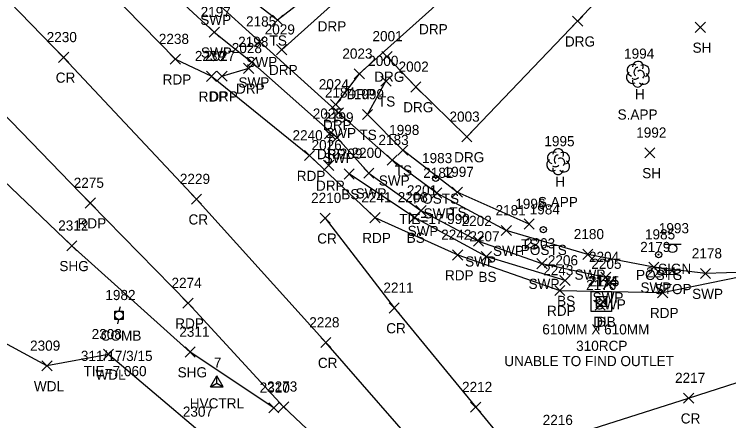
# Model space of a CAD drawing. Extents: x 1616726 to 1619875, y 273782 to 276557.
# Drawn here: x 1616834.7 to 1616975.5, y 276373.3 to 276453.4 of the extents above; entities that cross this region are included whole.
import ezdxf

# ---------------------------------------------------------------- set-up
doc = ezdxf.new("R2010")
doc.units = 0
for name, color, linetype in [('C_A', 7, 'Continuous'), ('C_I', 7, 'Continuous'), ('CPSM', 7, 'Continuous'), ('D_A', 7, 'Continuous'), ('D_C', 7, 'Continuous'), ('D_I', 7, 'Continuous'), ('D_TIC', 7, 'Continuous'), ('DS', 7, 'Continuous'), ('L_A', 7, 'Continuous'), ('L_C', 7, 'Continuous'), ('L_I', 7, 'Continuous'), ('L_TIC', 7, 'Continuous'), ('LAWA', 7, 'Continuous'), ('LELB', 7, 'Continuous'), ('LPST', 7, 'Continuous'), ('LTD', 7, 'Continuous'), ('P_A', 7, 'Continuous'), ('P_I', 7, 'Continuous'), ('P_TIC', 7, 'Continuous'), ('PET', 7, 'Continuous'), ('PRC', 7, 'Continuous'), ('PSU', 7, 'Continuous'), ('R_A', 7, 'Continuous'), ('R_I', 7, 'Continuous'), ('R_TIC', 7, 'Continuous'), ('RDG', 7, 'Continuous'), ('RDP', 7, 'Continuous'), ('RSW', 7, 'Continuous'), ('S_A', 7, 'Continuous'), ('S_C', 7, 'Continuous'), ('S_I', 7, 'Continuous'), ('SSGN', 7, 'Continuous'), ('U_A', 7, 'Continuous'), ('U_C', 7, 'Continuous'), ('U_I', 7, 'Continuous'), ('UP', 7, 'Continuous')]:
    doc.layers.add(name, color=color, linetype=linetype)

msp = doc.modelspace()

# ---------------------------------------------------------------- linework, layer by layer
at = {"layer": 'CPSM'}
for p, q in [((1616873.34, 276379.99), (1616874.59, 276382.16)), ((1616873.34, 276379.99), (1616874.59, 276382.16)), ((1616873.34, 276379.99), (1616874.59, 276382.16)), ((1616873.34, 276379.99), (1616874.59, 276382.16)), ((1616875.84, 276379.99), (1616874.59, 276382.16)), ((1616874.59, 276380.71), (1616874.59, 276382.16)), ((1616875.84, 276379.99), (1616874.59, 276382.16)), ((1616874.59, 276380.71), (1616874.59, 276382.16)), ((1616875.84, 276379.99), (1616874.59, 276382.16)), ((1616874.59, 276380.71), (1616874.59, 276382.16)), ((1616875.84, 276379.99), (1616874.59, 276382.16)), ((1616874.59, 276380.71), (1616874.59, 276382.16)), ((1616873.34, 276379.99), (1616874.59, 276380.71)), ((1616873.34, 276379.99), (1616874.59, 276380.71)), ((1616873.34, 276379.99), (1616874.59, 276380.71)), ((1616873.34, 276379.99), (1616874.59, 276380.71)), ((1616874.59, 276380.71), (1616874.59, 276380.71)), ((1616874.59, 276380.71), (1616875.84, 276379.99)), ((1616874.59, 276380.71), (1616874.59, 276380.71)), ((1616874.59, 276380.71), (1616875.84, 276379.99)), ((1616874.59, 276380.71), (1616874.59, 276380.71)), ((1616874.59, 276380.71), (1616875.84, 276379.99)), ((1616874.59, 276380.71), (1616874.59, 276380.71)), ((1616874.59, 276380.71), (1616875.84, 276379.99)), ((1616873.34, 276379.99), (1616875.84, 276379.99)), ((1616873.34, 276379.99), (1616875.84, 276379.99)), ((1616873.34, 276379.99), (1616875.84, 276379.99)), ((1616873.34, 276379.99), (1616875.84, 276379.99))]:
    msp.add_line(p, q, dxfattribs=at)
at = {"layer": 'D_TIC'}
for points in [[(1616949.69, 276395.76), (1616951.69, 276397.76)], [(1616951.69, 276395.76), (1616949.69, 276397.76)], [(1616949.15, 276395.04), (1616951.15, 276397.04)], [(1616951.15, 276395.04), (1616949.15, 276397.04)]]:
    msp.add_lwpolyline(points, dxfattribs=at)
at = {"layer": 'DS'}
for p, q in [((1616948.42, 276398.78), (1616952.42, 276398.78)), ((1616948.42, 276394.78), (1616948.42, 276398.78)), ((1616949.42, 276395.78), (1616949.42, 276397.78)), ((1616949.42, 276397.78), (1616951.42, 276397.78)), ((1616951.42, 276397.78), (1616951.42, 276395.78)), ((1616952.42, 276398.78), (1616952.42, 276394.78)), ((1616950.42, 276396.78), (1616950.42, 276396.78)), ((1616950.42, 276396.78), (1616950.42, 276396.78)), ((1616952.42, 276394.78), (1616948.42, 276394.78)), ((1616951.42, 276395.78), (1616949.42, 276395.78))]:
    msp.add_line(p, q, dxfattribs=at)
at = {"layer": 'L_TIC'}
for points in [[(1616885.59, 276451.23), (1616887.59, 276453.23)], [(1616887.59, 276451.23), (1616885.59, 276453.23)], [(1616968.9, 276449.81), (1616970.9, 276451.81)], [(1616970.9, 276449.81), (1616968.9, 276451.81)], [(1616906.95, 276439.21), (1616908.95, 276441.21)], [(1616908.95, 276439.21), (1616906.95, 276441.21)], [(1616903.32, 276432.64), (1616905.32, 276434.64)], [(1616905.32, 276432.64), (1616903.32, 276434.64)], [(1616910.27, 276425.6), (1616912.27, 276427.6)], [(1616912.27, 276425.6), (1616910.27, 276427.6)], [(1616958.96, 276425.08), (1616960.96, 276427.08)], [(1616960.96, 276425.08), (1616958.96, 276427.08)], [(1616899.7, 276420.92), (1616901.7, 276422.92)], [(1616901.7, 276420.92), (1616899.7, 276422.92)], [(1616921.01, 276417.34), (1616923.01, 276419.34)], [(1616923.01, 276417.34), (1616921.01, 276419.34)], [(1616912.6, 276412.34), (1616914.6, 276414.34)], [(1616914.6, 276412.34), (1616912.6, 276414.34)], [(1616935.18, 276411.04), (1616937.18, 276413.04)], [(1616937.18, 276411.04), (1616935.18, 276413.04)], [(1616926.73, 276404.63), (1616928.73, 276406.63)], [(1616928.73, 276404.63), (1616926.73, 276406.63)], [(1616942.24, 276399.9), (1616944.24, 276401.9)], [(1616944.24, 276399.9), (1616942.24, 276401.9)], [(1616852.28, 276385.36), (1616854.28, 276387.36)], [(1616854.28, 276385.36), (1616852.28, 276387.36)], [(1616840.14, 276383.08), (1616842.14, 276385.08)], [(1616842.14, 276383.08), (1616840.14, 276385.08)]]:
    msp.add_lwpolyline(points, dxfattribs=at)
at = {"layer": 'LAWA'}
msp.add_lwpolyline([(1616926.41, 276312.56), (1616914.58, 276324.87), (1616905.26, 276338.6), (1616897.95, 276344.34), (1616892.13, 276347.37), (1616881.86, 276360.64), (1616871.25, 276371.07), (1616853.28, 276386.36), (1616841.14, 276384.08), (1616808.16, 276401.96), (1616800.62, 276406.17), (1616775.17, 276427.7), (1616751.6, 276451.28), (1616729.6, 276454.6)], dxfattribs=at)
at = {"layer": 'LELB'}
for points in [[(1616901.03, 276463.44), (1616886.59, 276452.23), (1616871.01, 276464.24)], [(1616936.18, 276412.04), (1616922.01, 276418.34), (1616911.27, 276426.6), (1616904.32, 276433.64), (1616907.95, 276440.21)], [(1616943.24, 276400.9), (1616927.73, 276405.63), (1616913.6, 276413.34), (1616900.7, 276421.92)]]:
    msp.add_lwpolyline(points, dxfattribs=at)
at = {"layer": 'LPST'}
for centre, radius in [((1616917.75, 276421.05), 0.625), ((1616917.75, 276421.05), 0.0833), ((1616938.97, 276410.94), 0.625), ((1616938.97, 276410.94), 0.0833), ((1616961.69, 276406.02), 0.625), ((1616961.69, 276406.02), 0.0833)]:
    msp.add_circle(centre, radius, dxfattribs=at)
at = {"layer": 'LTD'}
for p, q in [((1616957.57, 276441.64), (1616957.57, 276441.64)), ((1616957.57, 276441.64), (1616957.57, 276441.64)), ((1616941.86, 276424.38), (1616941.86, 276424.38)), ((1616941.86, 276424.38), (1616941.86, 276424.38))]:
    msp.add_line(p, q, dxfattribs=at)
for centre in [(1616957.62, 276443.07), (1616941.91, 276425.82)]:
    msp.add_arc(centre, 1.05, 335.5272, 180.9563, dxfattribs=at)
for centre, major_axis, ratio, start_param, end_param in [((1616956.78, 276442.3), (1.21, -0.51), 0.895232, 1.570796, 4.712389), ((1616957.37, 276442.1), (-0.208, -0.792), 0.645439, 3.141593, 6.283185), ((1616958.62, 276442.22), (-1.14, -0.48), 0.949671, 1.570796, 4.712389), ((1616956.49, 276440.93), (0.58, -1.04), 0.959034, 3.141593, 6.283185), ((1616958.07, 276441.47), (-0.5, 0.667), 0.989748, 3.141593, 6.283185), ((1616958.57, 276440.8), (-1.09, 0.79), 0.841452, 1.570796, 4.712389), ((1616957.57, 276440.14), (0.26, 1.06), 0.942809, 1.570796, 4.712389), ((1616957.12, 276440.89), (-0.625, -0.083), 0.423636, 0, 3.141593), ((1616941.07, 276425.05), (1.21, -0.51), 0.895232, 1.570796, 4.712389), ((1616941.65, 276424.84), (-0.208, -0.792), 0.645439, 3.141593, 6.283185), ((1616942.9, 276424.97), (-1.14, -0.48), 0.949671, 1.570796, 4.712389), ((1616940.78, 276423.68), (0.58, -1.04), 0.959034, 3.141593, 6.283185), ((1616942.36, 276424.22), (-0.5, 0.667), 0.989748, 3.141593, 6.283185), ((1616942.86, 276423.55), (-1.09, 0.79), 0.841452, 1.570796, 4.712389), ((1616941.86, 276422.88), (0.26, 1.06), 0.942809, 1.570796, 4.712389), ((1616941.4, 276423.63), (-0.625, -0.083), 0.423636, 0, 3.141593)]:
    msp.add_ellipse(centre, major_axis=major_axis, ratio=ratio, start_param=start_param, end_param=end_param, dxfattribs=at)
at = {"layer": 'P_TIC'}
for points in [[(1616843.42, 276443.9), (1616845.42, 276445.9)], [(1616845.42, 276443.9), (1616843.42, 276445.9)], [(1616865.44, 276443.54), (1616867.44, 276445.54)], [(1616867.44, 276443.54), (1616865.44, 276445.54)], [(1616872.55, 276440.17), (1616874.55, 276442.17)], [(1616874.55, 276440.17), (1616872.55, 276442.17)], [(1616891.87, 276424.54), (1616893.87, 276426.54)], [(1616893.87, 276424.54), (1616891.87, 276426.54)], [(1616848.67, 276415.18), (1616850.67, 276417.18)], [(1616850.67, 276415.18), (1616848.67, 276417.18)], [(1616869.6, 276415.95), (1616871.6, 276417.95)], [(1616871.6, 276415.95), (1616869.6, 276417.95)], [(1616904.78, 276412.31), (1616906.78, 276414.31)], [(1616906.78, 276412.31), (1616904.78, 276414.31)], [(1616894.97, 276412.2), (1616896.97, 276414.2)], [(1616896.97, 276412.2), (1616894.97, 276414.2)], [(1616845.05, 276406.76), (1616847.05, 276408.76)], [(1616847.05, 276406.76), (1616845.05, 276408.76)], [(1616921.09, 276404.95), (1616923.09, 276406.95)], [(1616923.09, 276404.95), (1616921.09, 276406.95)], [(1616941.2, 276397.95), (1616943.2, 276399.95)], [(1616943.2, 276397.95), (1616941.2, 276399.95)], [(1616961.48, 276397.53), (1616963.48, 276399.53)], [(1616963.48, 276397.53), (1616961.48, 276399.53)], [(1616867.94, 276395.45), (1616869.94, 276397.45)], [(1616869.94, 276395.45), (1616867.94, 276397.45)], [(1616908.57, 276394.51), (1616910.57, 276396.51)], [(1616910.57, 276394.51), (1616908.57, 276396.51)], [(1616895.09, 276387.68), (1616897.09, 276389.68)], [(1616897.09, 276387.68), (1616895.09, 276389.68)], [(1616868.35, 276385.82), (1616870.35, 276387.82)], [(1616870.35, 276385.82), (1616868.35, 276387.82)], [(1616966.61, 276376.73), (1616968.61, 276378.73)], [(1616968.61, 276376.73), (1616966.61, 276378.73)], [(1616884.84, 276374.81), (1616886.84, 276376.81)], [(1616886.84, 276374.81), (1616884.84, 276376.81)], [(1616886.78, 276375.03), (1616888.78, 276377.03)], [(1616888.78, 276375.03), (1616886.78, 276377.03)], [(1616924.64, 276374.94), (1616926.64, 276376.94)], [(1616926.64, 276374.94), (1616924.64, 276376.94)]]:
    msp.add_lwpolyline(points, dxfattribs=at)
at = {"layer": 'PET'}
for points in [[(1616787.59, 276521.58), (1616809.24, 276501.22), (1616830.38, 276480.01), (1616850.02, 276461.38), (1616866.44, 276444.54), (1616873.55, 276441.17), (1616892.87, 276425.54), (1616905.78, 276413.31), (1616922.09, 276405.95), (1616942.2, 276398.95), (1616962.48, 276398.53), (1616981.09, 276402.37)], [(1616900.38, 276364.1), (1616887.78, 276376.03), (1616868.94, 276396.45), (1616849.67, 276416.18), (1616824.34, 276442.26), (1616800.52, 276466.55), (1616781.83, 276484.67), (1616766.23, 276499.7)]]:
    msp.add_lwpolyline(points, dxfattribs=at)
at = {"layer": 'PRC'}
for points in [[(1616953.09, 276321.77), (1616937.3, 276341.18), (1616917.35, 276364.38), (1616896.09, 276388.68), (1616870.6, 276416.95), (1616844.42, 276444.9), (1616816.58, 276473.52), (1616795.84, 276493.99), (1616777.17, 276512.19)], [(1616941.59, 276369.44), (1616967.61, 276377.73), (1616992.45, 276385.73), (1617015.18, 276393.53), (1617040, 276403.88), (1617060.6, 276414.36), (1617077.78, 276424.7), (1617090.54, 276433.25), (1617097.77, 276438.74)], [(1616895.97, 276413.2), (1616909.57, 276395.51), (1616925.64, 276375.94), (1616938.47, 276360.41), (1616951.96, 276344.02), (1616962.87, 276330.95)]]:
    msp.add_lwpolyline(points, dxfattribs=at)
at = {"layer": 'PSU'}
msp.add_lwpolyline([(1616885.84, 276375.81), (1616869.35, 276386.82), (1616846.05, 276407.76), (1616827.94, 276424.97), (1616809.53, 276443.22), (1616786.02, 276468.38), (1616760.28, 276493.66)], dxfattribs=at)
at = {"layer": 'R_TIC'}
for points in [[(1616944.73, 276451.03), (1616946.73, 276453.03)], [(1616946.73, 276451.03), (1616944.73, 276453.03)], [(1616873.12, 276448.86), (1616875.12, 276450.86)], [(1616875.12, 276448.86), (1616873.12, 276450.86)], [(1616882.06, 276446.99), (1616884.06, 276448.99)], [(1616884.06, 276446.99), (1616882.06, 276448.99)], [(1616886.4, 276445.41), (1616888.4, 276447.41)], [(1616888.4, 276445.41), (1616886.4, 276447.41)], [(1616907.14, 276444.08), (1616909.14, 276446.08)], [(1616909.14, 276444.08), (1616907.14, 276446.08)], [(1616880.51, 276442.96), (1616882.51, 276444.96)], [(1616882.51, 276442.96), (1616880.51, 276444.96)], [(1616879.9, 276441.74), (1616881.9, 276443.74)], [(1616881.9, 276441.74), (1616879.9, 276443.74)], [(1616901.69, 276440.64), (1616903.69, 276442.64)], [(1616903.69, 276440.64), (1616901.69, 276442.64)], [(1616874.62, 276440.2), (1616876.62, 276442.2)], [(1616876.62, 276440.2), (1616874.62, 276442.2)], [(1616912.85, 276438.07), (1616914.85, 276440.07)], [(1616914.85, 276438.07), (1616912.85, 276440.07)], [(1616897.05, 276434.6), (1616899.05, 276436.6)], [(1616899.05, 276434.6), (1616897.05, 276436.6)], [(1616897.61, 276432.98), (1616899.61, 276434.98)], [(1616899.61, 276432.98), (1616897.61, 276434.98)], [(1616895.86, 276428.82), (1616897.86, 276430.82)], [(1616897.86, 276428.82), (1616895.86, 276430.82)], [(1616897.31, 276428.07), (1616899.31, 276430.07)], [(1616899.31, 276428.07), (1616897.31, 276430.07)], [(1616922.89, 276428.22), (1616924.89, 276430.22)], [(1616924.89, 276428.22), (1616922.89, 276430.22)], [(1616908.17, 276423.63), (1616910.17, 276425.63)], [(1616910.17, 276423.63), (1616908.17, 276425.63)], [(1616895.67, 276422.61), (1616897.67, 276424.61)], [(1616897.67, 276422.61), (1616895.67, 276424.61)], [(1616903.59, 276421.09), (1616905.59, 276423.09)], [(1616905.59, 276421.09), (1616903.59, 276423.09)], [(1616916.99, 276417.15), (1616918.99, 276419.15)], [(1616918.99, 276417.15), (1616916.99, 276419.15)], [(1616913.85, 276413.69), (1616915.85, 276415.69)], [(1616915.85, 276413.69), (1616913.85, 276415.69)], [(1616930.67, 276409.77), (1616932.67, 276411.77)], [(1616932.67, 276409.77), (1616930.67, 276411.77)], [(1616925.19, 276407.67), (1616927.19, 276409.67)], [(1616927.19, 276407.67), (1616925.19, 276409.67)], [(1616946.75, 276405.07), (1616948.75, 276407.07)], [(1616948.75, 276405.07), (1616946.75, 276407.07)], [(1616937.69, 276403.25), (1616939.69, 276405.25)], [(1616939.69, 276403.25), (1616937.69, 276405.25)], [(1616959.75, 276402.53), (1616961.75, 276404.53)], [(1616961.75, 276402.53), (1616959.75, 276404.53)], [(1616969.93, 276401.28), (1616971.93, 276403.28)], [(1616971.93, 276401.28), (1616969.93, 276403.28)], [(1616950.3, 276400.58), (1616952.3, 276402.58)], [(1616952.3, 276400.58), (1616950.3, 276402.58)], [(1616950.76, 276399.21), (1616952.76, 276401.21)], [(1616952.76, 276399.21), (1616950.76, 276401.21)]]:
    msp.add_lwpolyline(points, dxfattribs=at)
at = {"layer": 'RDG'}
msp.add_lwpolyline([(1616908.14, 276445.08), (1616913.85, 276439.07), (1616923.89, 276429.22), (1616945.73, 276452.03), (1616962.21, 276469.48)], dxfattribs=at)
at = {"layer": 'RDP'}
for points in [[(1616887.4, 276446.41), (1616896.99, 276455.02), (1616909.3, 276466.91), (1616924.67, 276481)], [(1617035.74, 276419.76), (1617032.19, 276427.66), (1617017.5, 276442.32), (1617002.8, 276454.02), (1616987.53, 276462.11), (1616971.33, 276468.46), (1616960.11, 276471), (1616943.03, 276471.75), (1616932.72, 276469.15), (1616916.98, 276454.45), (1616902.69, 276441.64), (1616898.05, 276435.6)], [(1616875.62, 276441.2), (1616880.9, 276442.74)], [(1616896.86, 276429.82), (1616896.67, 276423.61)]]:
    msp.add_lwpolyline(points, dxfattribs=at)
at = {"layer": 'RSW'}
for points in [[(1616979.18, 276402.58), (1616970.93, 276402.28), (1616960.75, 276403.53), (1616947.75, 276406.07), (1616931.67, 276410.77), (1616917.99, 276418.15), (1616909.17, 276424.63), (1616898.61, 276433.98), (1616883.06, 276447.99), (1616873.99, 276456.3), (1616860.19, 276469.07), (1616843.86, 276484.23), (1616830.87, 276497.35), (1616815.83, 276511.33), (1616796.2, 276529.55)], [(1616793, 276526.57), (1616806.64, 276513.9), (1616822.44, 276499.44), (1616842.9, 276479.1), (1616862.42, 276460.7), (1616874.12, 276449.86), (1616881.51, 276443.96), (1616898.31, 276429.07), (1616904.59, 276422.09), (1616914.85, 276414.69), (1616926.19, 276408.67), (1616938.69, 276404.25), (1616951.3, 276401.58), (1616951.76, 276400.21)]]:
    msp.add_lwpolyline(points, dxfattribs=at)
at = {"layer": 'SSGN'}
for p, q in [((1616962.8, 276408.08), (1616966.13, 276408.08)), ((1616964.45, 276407.25), (1616964.45, 276407.25))]:
    msp.add_line(p, q, dxfattribs=at)
msp.add_circle((1616964.45, 276407.25), 0.833, dxfattribs=at)
at = {"layer": 'UP'}
for p, q in [((1616854.5, 276393.23), (1616854.5, 276394.9)), ((1616854.5, 276394.9), (1616856.17, 276394.9)), ((1616855.58, 276395.73), (1616855.33, 276394.9)), ((1616856.17, 276394.9), (1616856.17, 276393.23)), ((1616856.17, 276393.23), (1616854.5, 276393.23)), ((1616855.08, 276392.4), (1616855.33, 276393.23)), ((1616855.33, 276394.06), (1616855.33, 276394.06))]:
    msp.add_line(p, q, dxfattribs=at)
msp.add_circle((1616855.33, 276394.06), 0.833, dxfattribs=at)

# ---------------------------------------------------------------- texts
at = {"layer": 'C_A'}
msp.add_text('HVCTRL', height=2, dxfattribs=at).set_placement((1616869.28, 276375.71))
msp.add_text('HVCTRL', height=2, dxfattribs=at).set_placement((1616869.28, 276375.71))
msp.add_text('HVCTRL', height=2, dxfattribs=at).set_placement((1616869.28, 276375.71))
msp.add_text('HVCTRL', height=2, dxfattribs=at).set_placement((1616869.28, 276375.71))
at = {"layer": 'C_I'}
msp.add_text('7', height=2, dxfattribs=at).set_placement((1616874.02, 276383.71))
msp.add_text('7', height=2, dxfattribs=at).set_placement((1616874.02, 276383.71))
msp.add_text('7', height=2, dxfattribs=at).set_placement((1616874.02, 276383.71))
msp.add_text('7', height=2, dxfattribs=at).set_placement((1616874.02, 276383.71))
at = {"layer": 'D_A'}
for s, p in [('DIB', (1616948.79, 276391.76)), ('DI', (1616949.48, 276391.78)), ('P', (1616949.53, 276391.04))]:
    msp.add_text(s, height=2, dxfattribs=at).set_placement(p)
at = {"layer": 'D_C'}
for s, p in [('610MM X 610MM', (1616938.76, 276390.29)), ('310RCP', (1616945.43, 276387.04)), ('UNABLE TO FIND OUTLET', (1616931.28, 276384.04))]:
    msp.add_text(s, height=2, dxfattribs=at).set_placement(p)
at = {"layer": 'D_I'}
for s, p in [('2174', (1616947.73, 276399.78)), ('2175', (1616947.99, 276399.76)), ('2176', (1616947.4, 276399.04))]:
    msp.add_text(s, height=2, dxfattribs=at).set_placement(p)
at = {"layer": 'L_A'}
for s, p in [('TS', (1616885, 276447.23)), ('SH', (1616968.38, 276445.81)), ('H', (1616957.01, 276436.64)), ('TS', (1616906.36, 276435.21)), ('TS', (1616902.72, 276428.64)), ('TS', (1616909.68, 276421.6)), ('SH', (1616958.45, 276421.08)), ('H', (1616941.3, 276419.38)), ('BS', (1616899.14, 276416.92)), ('POSTS', (1616913.3, 276416.05)), ('TS', (1616920.42, 276413.34)), ('BS', (1616912.04, 276408.34)), ('TS', (1616934.59, 276407.04)), ('POSTS', (1616934.52, 276405.94)), ('POSTS', (1616957.24, 276401.02)), ('BS', (1616926.17, 276400.63)), ('BS', (1616941.68, 276395.9)), ('WDL', (1616850.7, 276381.36)), ('WDL', (1616838.56, 276379.08))]:
    msp.add_text(s, height=2, dxfattribs=at).set_placement(p)
at = {"layer": 'L_C'}
for s, p in [('S.APP', (1616953.6, 276432.64)), ('S.APP', (1616937.89, 276415.38)), ('TIE=17.990', (1616910.57, 276412.05))]:
    msp.add_text(s, height=2, dxfattribs=at).set_placement(p)
at = {"layer": 'L_I'}
for s, p in [('1994', (1616954.88, 276444.64)), ('2000', (1616904.45, 276443.21)), ('1999', (1616901.61, 276436.64)), ('1998', (1616908.58, 276429.6)), ('1992', (1616957.27, 276429.08)), ('1995', (1616939.17, 276427.38)), ('2209', (1616897.35, 276424.92)), ('1983', (1616915.06, 276424.05)), ('1997', (1616919.32, 276421.34)), ('2208', (1616910.26, 276416.34)), ('1996', (1616933.43, 276415.04)), ('1984', (1616936.28, 276413.94)), ('2207', (1616924.39, 276408.63)), ('1985', (1616959, 276409.02)), ('2206', (1616939.85, 276403.9)), ('2308', (1616849.94, 276389.36)), ('2309', (1616837.8, 276387.08)), ('2307', (1616867.91, 276374.07))]:
    msp.add_text(s, height=2, dxfattribs=at).set_placement(p)
at = {"layer": 'P_A'}
for s, p in [('CR', (1616842.86, 276439.9)), ('RDP', (1616863.93, 276439.54)), ('RDP', (1616871.03, 276436.17)), ('RDP', (1616890.36, 276420.54)), ('RDP', (1616847.16, 276411.18)), ('CR', (1616869.03, 276411.95)), ('CR', (1616894.4, 276408.2)), ('RDP', (1616903.27, 276408.31)), ('SHG', (1616843.58, 276402.76)), ('RDP', (1616919.58, 276400.95)), ('RDP', (1616939.69, 276393.95)), ('RDP', (1616959.97, 276393.53)), ('RDP', (1616866.42, 276391.45)), ('CR', (1616908, 276390.51)), ('CR', (1616894.53, 276383.68)), ('SHG', (1616866.89, 276381.82)), ('CR', (1616966.05, 276372.73))]:
    msp.add_text(s, height=2, dxfattribs=at).set_placement(p)
at = {"layer": 'P_I'}
for s, p in [('2230', (1616841.08, 276447.9)), ('2238', (1616863.18, 276447.54)), ('2239', (1616870.28, 276444.17)), ('2240', (1616889.53, 276428.54)), ('2229', (1616867.33, 276419.95)), ('2275', (1616846.41, 276419.18)), ('2210', (1616893.19, 276416.2)), ('2241', (1616903.09, 276416.31)), ('2312', (1616843.35, 276410.76)), ('2242', (1616918.83, 276408.95)), ('2243', (1616938.94, 276401.95)), ('2244', (1616959.22, 276401.53)), ('2274', (1616865.68, 276399.45)), ('2211', (1616907.44, 276398.51)), ('2228', (1616892.83, 276391.68)), ('2311', (1616867.22, 276389.82)), ('2217', (1616964.92, 276380.73)), ('2310', (1616883.06, 276378.81)), ('2273', (1616884.52, 276379.03)), ('2212', (1616922.94, 276378.94)), ('2216', (1616938.84, 276372.44))]:
    msp.add_text(s, height=2, dxfattribs=at).set_placement(p)
at = {"layer": 'R_A'}
for s, p in [('SWP', (1616871.35, 276451.3)), ('DRP', (1616894.48, 276450.02)), ('DRP', (1616914.47, 276449.45)), ('DRG', (1616943.22, 276447.03)), ('SWP', (1616871.48, 276444.86)), ('SWP', (1616880.42, 276442.99)), ('DRP', (1616884.89, 276441.41)), ('DRG', (1616905.63, 276440.08)), ('DRP', (1616878.39, 276437.74)), ('SWP', (1616878.87, 276438.96)), ('DRP', (1616900.18, 276436.64)), ('DRP', (1616873.11, 276436.2)), ('DRG', (1616911.34, 276434.07)), ('DRP', (1616895.54, 276430.6)), ('SWP', (1616895.97, 276428.98)), ('DRP', (1616894.35, 276424.82)), ('SWP', (1616895.67, 276424.07)), ('DRG', (1616921.38, 276424.22)), ('SWP', (1616906.53, 276419.63)), ('DRP', (1616894.16, 276418.61)), ('SWP', (1616901.95, 276417.09)), ('SWP', (1616915.35, 276413.15)), ('SWP', (1616912.21, 276409.69)), ('SWP', (1616929.04, 276405.77)), ('SWP', (1616923.55, 276403.67)), ('SWP', (1616945.11, 276401.07)), ('SWP', (1616936.05, 276399.25)), ('SWP', (1616958.11, 276398.53)), ('SWP', (1616968.29, 276397.28)), ('SWP', (1616948.66, 276396.58)), ('SWP', (1616949.12, 276395.21))]:
    msp.add_text(s, height=2, dxfattribs=at).set_placement(p)
at = {"layer": 'R_I'}
for s, p in [('2197', (1616871.42, 276452.86)), ('2185', (1616880.37, 276450.99)), ('2029', (1616884.05, 276449.41)), ('2001', (1616905.29, 276448.08)), ('2198', (1616878.82, 276446.96)), ('2028', (1616877.56, 276445.74)), ('2027', (1616872.28, 276444.2)), ('2023', (1616899.35, 276444.64)), ('2002', (1616910.43, 276442.07)), ('2024', (1616894.71, 276438.6)), ('2184', (1616895.91, 276436.98)), ('2025', (1616893.52, 276432.82)), ('2199', (1616895.61, 276432.07)), ('2003', (1616920.47, 276432.22)), ('2026', (1616893.28, 276426.61)), ('2183', (1616906.47, 276427.63)), ('2200', (1616901.16, 276425.09)), ('2182', (1616915.3, 276421.15)), ('2201', (1616912.08, 276417.69)), ('2181', (1616929.55, 276413.77)), ('2202', (1616922.85, 276411.67)), ('2180', (1616944.97, 276409.07)), ('2203', (1616935.35, 276407.25)), ('2179', (1616958.05, 276406.53)), ('2178', (1616968.23, 276405.28)), ('2204', (1616947.96, 276404.58)), ('2205', (1616948.42, 276403.21))]:
    msp.add_text(s, height=2, dxfattribs=at).set_placement(p)
at = {"layer": 'S_A'}
msp.add_text('SIGN', height=2, dxfattribs=at).set_placement((1616961.58, 276402.23))
at = {"layer": 'S_C'}
msp.add_text('STOP', height=2, dxfattribs=at).set_placement((1616960.91, 276398.23))
at = {"layer": 'S_I'}
msp.add_text('1993', height=2, dxfattribs=at).set_placement((1616961.73, 276410.23))
at = {"layer": 'U_A'}
msp.add_text('COMB', height=2, dxfattribs=at).set_placement((1616851.72, 276389.06))
at = {"layer": 'U_C'}
for s, p in [('311/17/3/15', (1616847.82, 276385.06)), ('TIE=7.060', (1616848.35, 276382.06))]:
    msp.add_text(s, height=2, dxfattribs=at).set_placement(p)
at = {"layer": 'U_I'}
msp.add_text('1982', height=2, dxfattribs=at).set_placement((1616852.64, 276397.06))

doc.saveas('drawing.dxf')
